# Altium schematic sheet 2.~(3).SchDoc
size 420 x 297 mm
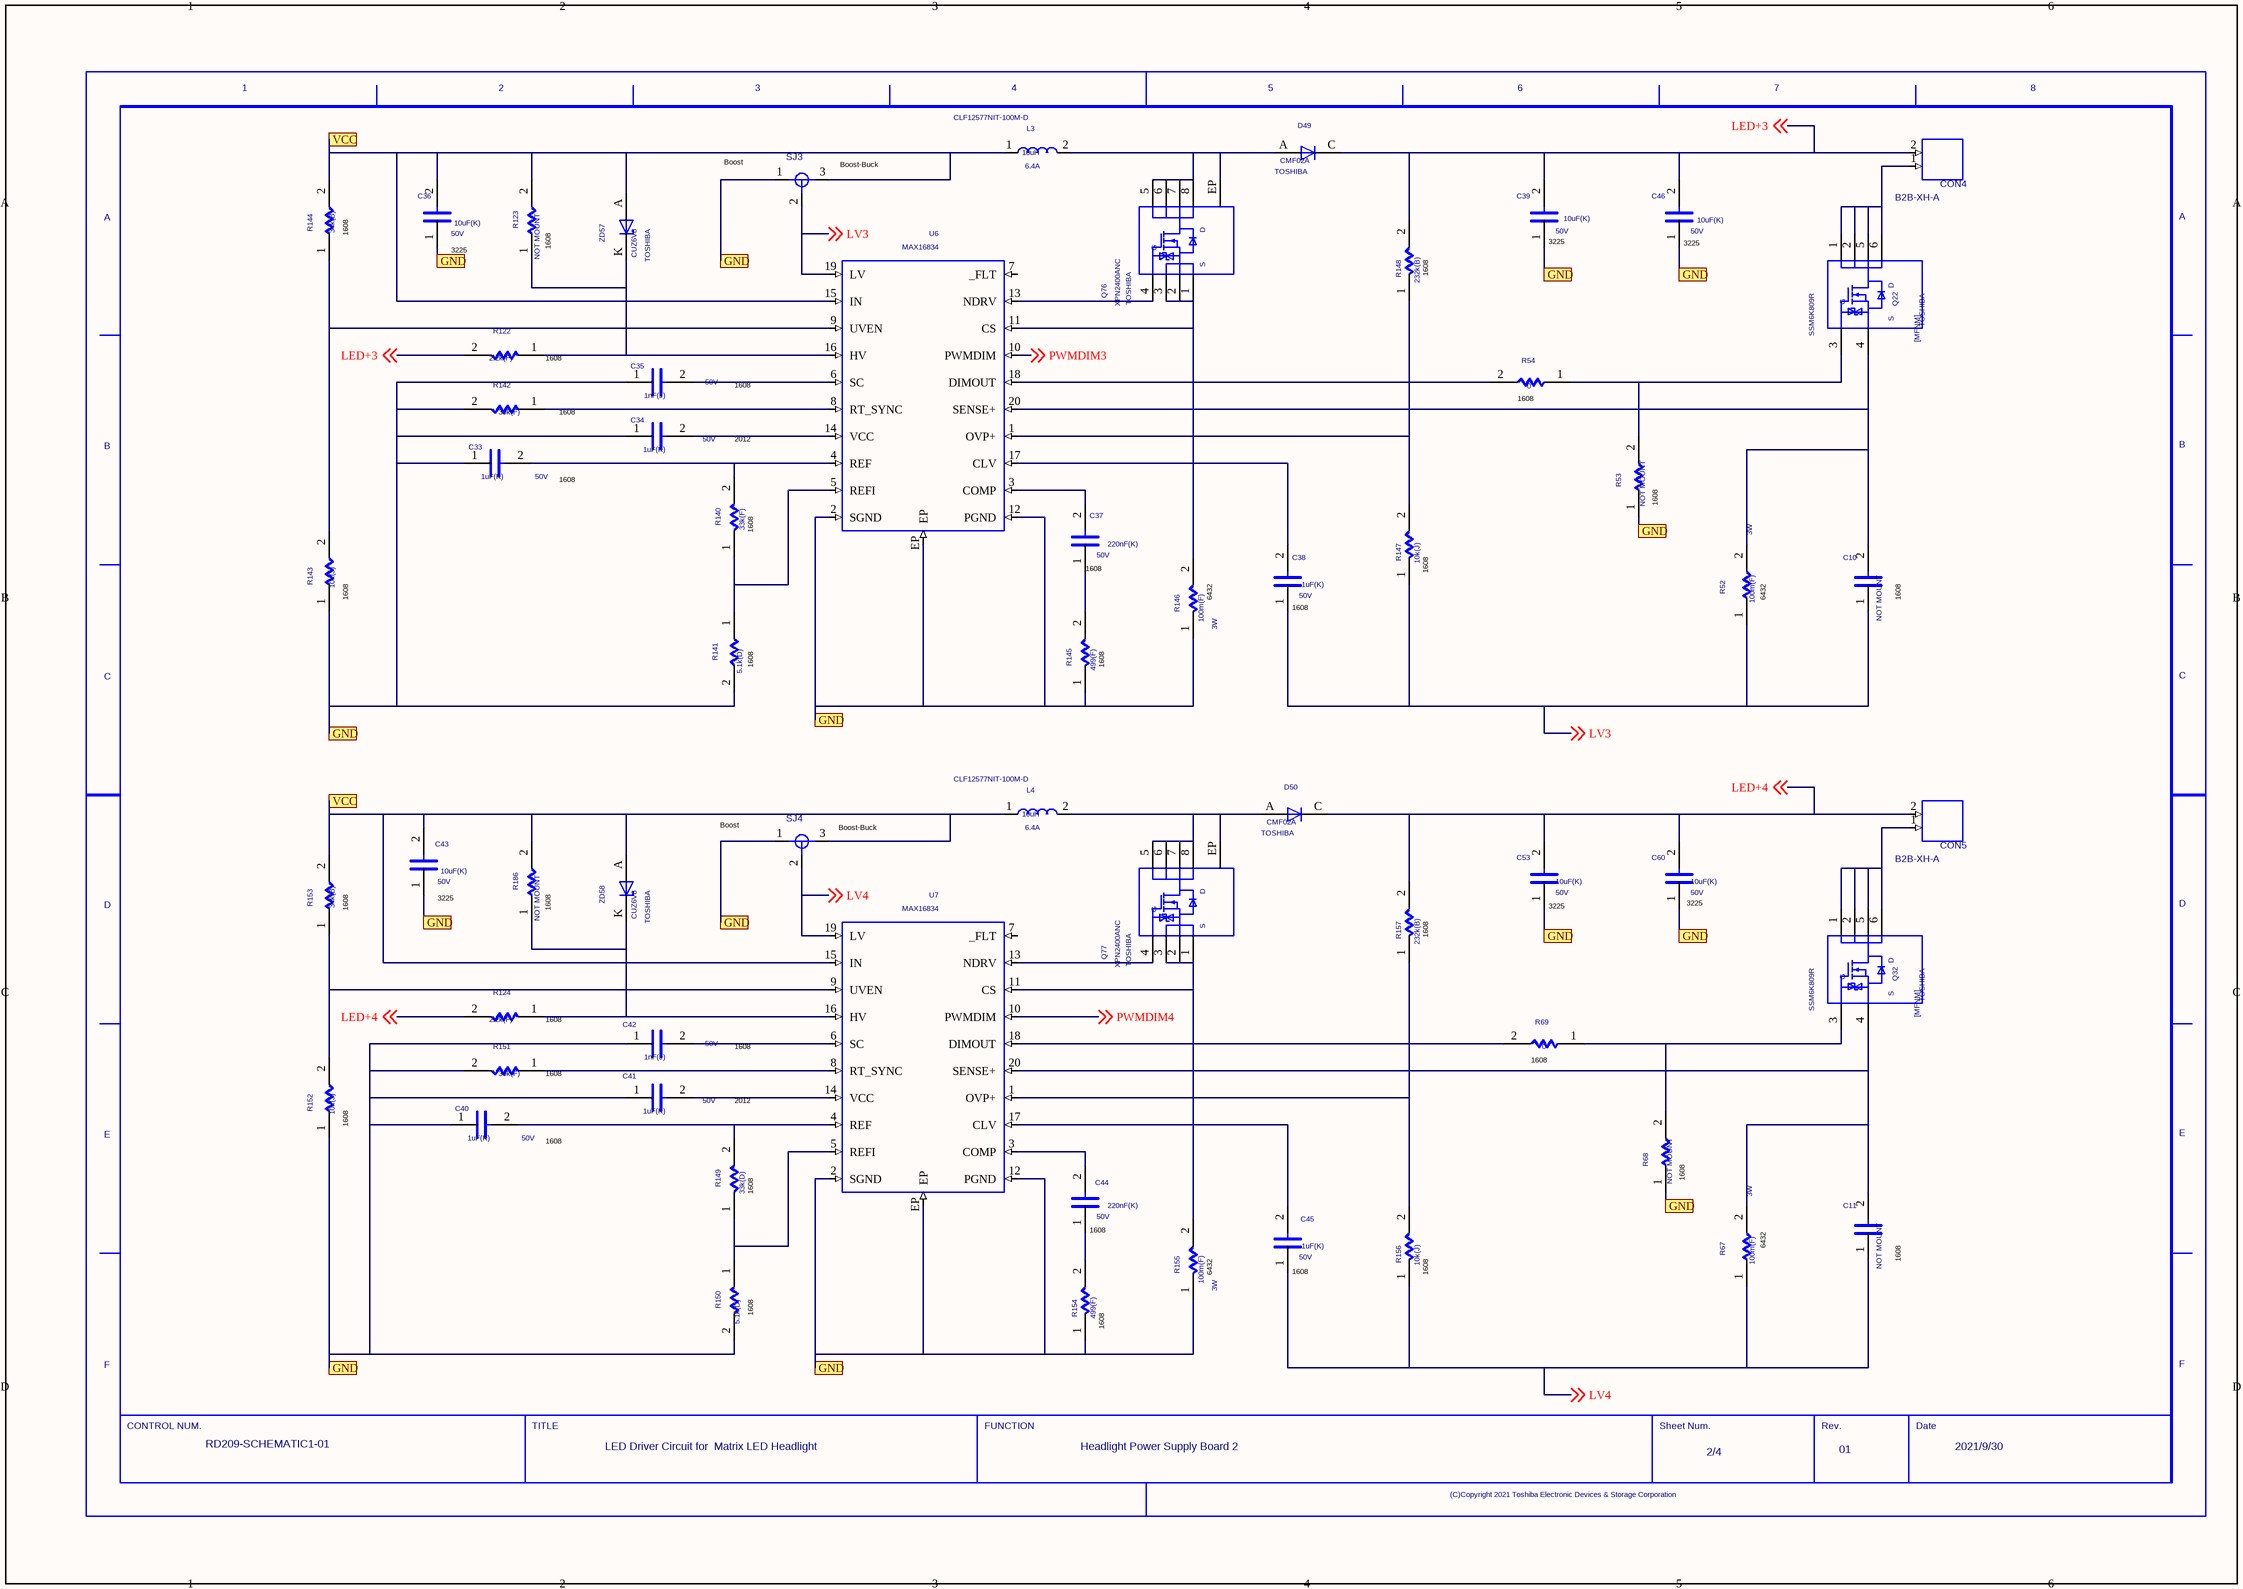
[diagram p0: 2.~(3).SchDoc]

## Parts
C10  NOTMOUNT: NOT MOUNT  (hidden comment: C)
C11  NOTMOUNT: NOT MOUNT  (hidden comment: C)
C33  VAL2: 50V  VAL1: 1uF(K)  (hidden comment: C)
C34  VAL2: 50V  VAL1: 1uF(K)  (hidden comment: C)
C35  VAL2: 50V  VAL1: 1nF(J)  (hidden comment: C)
C36  VAL2: 50V  VAL1: 10uF(K)  (hidden comment: C)
C37  VAL2: 50V  VAL1: 220nF(K)  (hidden comment: C)
C38  VAL2: 50V  VAL1: 1uF(K)  (hidden comment: C)
C39  VAL2: 50V  VAL1: 10uF(K)  (hidden comment: C)
C40  VAL2: 50V  VAL1: 1uF(K)  (hidden comment: C)
C41  VAL2: 50V  VAL1: 1uF(K)  (hidden comment: C)
C42  VAL2: 50V  VAL1: 1nF(J)  (hidden comment: C)
C43  VAL2: 50V  VAL1: 10uF(K)  (hidden comment: C)
C44  VAL2: 50V  VAL1: 220nF(K)  (hidden comment: C)
C45  VAL2: 50V  VAL1: 1uF(K)  (hidden comment: C)
C46  VAL2: 50V  VAL1: 10uF(K)  (hidden comment: C)
C53  VAL2: 50V  VAL1: 10uF(K)  (hidden comment: C)
C60  VAL2: 50V  VAL1: 10uF(K)  (hidden comment: C)
CON4  B2B-XH-A  [B2B-XH-A]
CON5  B2B-XH-A  [B2B-XH-A]
D49  USERCOMPTEXT3: TOSHIBA  VAL3: CMF02A  (hidden comment: D)
D50  USERCOMPTEXT3: TOSHIBA  VAL3: CMF02A  (hidden comment: D)
L3  VAL3: CLF12577NIT-100M-D  VAL2: 6.4A  VAL1: 10uH  (hidden comment: L)
L4  VAL3: CLF12577NIT-100M-D  VAL2: 6.4A  VAL1: 10uH  (hidden comment: L)
Q22  USERCOMPTEXT3: TOSHIBA  VAL3: SSM6K809R  (hidden comment: MFNM)
Q32  USERCOMPTEXT3: TOSHIBA  VAL3: SSM6K809R  (hidden comment: MFNM)
Q76  USERCOMPTEXT3: TOSHIBA  VAL3: XPN2400ANC  (hidden comment: MFNKR1)
Q77  USERCOMPTEXT3: TOSHIBA  VAL3: XPN2400ANC  (hidden comment: MFNKR1)
R52  VAL2: 3W  VAL1: 100m(F)  (hidden comment: R)
R53  NOTMOUNT: NOT MOUNT  (hidden comment: R)
R54  VAL1: 0  (hidden comment: R)
R67  VAL2: 3W  VAL1: 100m(F)  (hidden comment: R)
R68  NOTMOUNT: NOT MOUNT  (hidden comment: R)
R69  VAL1: 0  (hidden comment: R)
R122  VAL1: 2.2k(F)  (hidden comment: R)
R123  NOTMOUNT: NOT MOUNT  (hidden comment: R)
R124  VAL1: 2.2k(F)  (hidden comment: R)
R140  VAL1: 33k(F)  (hidden comment: R)
R141  VAL1: 5.1k(D)  (hidden comment: R)
R142  VAL1: 39k(F)  (hidden comment: R)
R143  VAL1: 10k(J)  (hidden comment: R)
R144  VAL1: 34k(B)  (hidden comment: R)
R145  VAL1: 499(F)  (hidden comment: R)
R146  VAL2: 3W  VAL1: 100m(F)  (hidden comment: R)
R147  VAL1: 10k(J)  (hidden comment: R)
R148  VAL1: 232k(B)  (hidden comment: R)
R149  VAL1: 33k(D)  (hidden comment: R)
R150  VAL1: 5.1k(D)  (hidden comment: R)
R151  VAL1: 39k(F)  (hidden comment: R)
R152  VAL1: 10k(J)  (hidden comment: R)
R153  VAL1: 34k(B)  (hidden comment: R)
R154  VAL1: 499(F)  (hidden comment: R)
R155  VAL2: 3W  VAL1: 100m(F)  (hidden comment: R)
R156  VAL1: 10k(J)  (hidden comment: R)
R157  VAL1: 232k(B)  (hidden comment: R)
R186  NOTMOUNT: NOT MOUNT  (hidden comment: R)
SJ3  SJ2W  (value not drawn)
SJ4  SJ2W  (value not drawn)
U6  MAX16834
U7  MAX16834
U?  DATE: 2021/9/30  REVISION: 01  FUNCTION: Headlight Power Supply Board 2  SHEETNUMBER: 2/4  TITLE: LED Driver Circuit for / Matrix LED Headlight  DRAWINGNUMBER: RD209-SCHEMATIC1-01  (hidden comment: WAKU_DEF100)
ZD57  USERCOMPTEXT3: TOSHIBA  VAL3: CUZ6V8  (hidden comment: ZD)
ZD58  USERCOMPTEXT3: TOSHIBA  VAL3: CUZ6V8  (hidden comment: ZD)

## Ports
GND, VCC

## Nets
GND: C33.1 C34.1 C35.1 C36.1 C39.1 C40.1 C41.1 C42.1 C43.1 C46.1 C53.1 C60.1 R53.1 R68.1 R141.2 R142.2 R143.1 R145.1 R146.1 R150.2 R151.2 R152.1 R154.1 R155.1 SJ3.1 SJ4.1 U6.2(SGND) U6.12(PGND) U6.EP U7.2(SGND) U7.12(PGND) U7.EP ; port GND
LED+3: C39.2 C46.2 CON4.2 D49.C R122.2 R148.2 ; off-sheet LED+3
LED+4: C53.2 C60.2 CON5.2 D50.C R124.2 R157.2 ; off-sheet LED+4
LV3: C10.1 C38.1 R52.1 R147.1 SJ3.2 U6.19(LV) ; off-sheet LV3
LV4: C11.1 C45.1 R67.1 R156.1 SJ4.2 U7.19(LV) ; off-sheet LV4
PWMDIM3: U6.10(PWMDIM) ; off-sheet PWMDIM3
PWMDIM4: U7.10(PWMDIM) ; off-sheet PWMDIM4
SIG668: R142.1 U6.8(RT_SYNC)
SIG669: Q77.1 Q77.2 Q77.3 R155.2 U7.11(CS)
SIG670: D50.A L4.2 Q77.5 Q77.6 Q77.7 Q77.8 Q77.EP
SIG671: CON5.1 Q32.1 Q32.2 Q32.5 Q32.6
SIG673: C44.2 U7.3(COMP)
SIG674: C45.2 U7.17(CLV)
SIG675: R156.2 R157.1 U7.1(OVP+)
SIG676: R69.2 U7.18(DIMOUT)
SIG677: R147.2 R148.1 U6.1(OVP+)
SIG679: R143.2 R144.1 U6.9(UVEN)
SIG680: R151.1 U7.8(RT_SYNC)
SIG681: C42.2 U7.6(SC)
SIG682: Q32.3 R68.2 R69.1
SIG683: R54.2 U6.18(DIMOUT)
SIG686: R124.1 R186.1 U7.16(HV) ZD58.K(C)
SIG690: R149.1 R150.1 U7.5(REFI)
SIG691: R152.2 R153.1 U7.9(UVEN)
SIG693: C40.2 R149.2 U7.4(REF)
SIG694: Q77.4 U7.13(NDRV)
SIG695: C41.2 U7.14(VCC)
SIG696: C10.2 Q22.4 R52.2 U6.20(SENSE+)
SIG697: D49.A L3.2 Q76.5 Q76.6 Q76.7 Q76.8 Q76.EP
SIG698: R122.1 R123.1 U6.16(HV) ZD57.K(C)
SIG699: Q76.1 Q76.2 Q76.3 R146.2 U6.11(CS)
SIG700: C37.1 R145.2
SIG702: C44.1 R154.2
SIG704: Q22.3 R53.2 R54.1
SIG705: CON4.1 Q22.1 Q22.2 Q22.5 Q22.6
SIG707: R140.1 R141.1 U6.5(REFI)
SIG709: C11.2 Q32.4 R67.2 U7.20(SENSE+)
SIG710: C37.2 U6.3(COMP)
SIG711: C35.2 U6.6(SC)
SIG712: C33.2 R140.2 U6.4(REF)
SIG713: C38.2 U6.17(CLV)
SIG715: C34.2 U6.14(VCC)
SIG717: Q76.4 U6.13(NDRV)
VCC: C36.2 C43.2 L3.1 L4.1 R123.2 R144.2 R153.2 R186.2 SJ3.3 SJ4.3 U6.15(IN) U7.15(IN) ZD57.A ZD58.A ; port VCC

Not connected (* = marked no-connect by the designer): U6 7(_FLT); U7 7(_FLT)

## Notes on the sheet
- (near SJ3) Boost
- (near SJ3) Boost-Buck
- (near R144) 1608
- (near C36) 3225
- (near R123) 1608
- (near C39) 3225
- (near C46) 3225
- (near R148) 1608
- (near R122) 1608
- 1608
- (near R142) 1608
- 2012
- (near R54) 1608
- (near R140) 1608
- (near R53) 1608
- (near R143) 1608
- (near C37) 1608
- (near R146) 6432
- (near R147) 1608
- (near R52) 6432
- (near C10) 1608
- (near R141) 1608
- (near R145) 1608
- (near C38) 1608
- (near SJ4) Boost
- (near SJ4) Boost-Buck
- (near R153) 1608
- (near C43) 3225
- (near R186) 1608
- (near R157) 1608
- (near C53) 3225
- (near C60) 3225
- (near R124) 1608
- (near R69) 1608
- (near R152) 1608
- (near R151) 1608
- (near R149) 1608
- (near R68) 1608
- (near C44) 1608
- (near R155) 6432
- (near C45) 1608
- (near R156) 1608
- (near R67) 6432
- (near C11) 1608
- (near R150) 1608
- (near R154) 1608

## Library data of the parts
C10 = C: TIME: 17:22:43; UPDATEUSER: t5459927; SAVECOUNT: 1; OriginalSymbolOrigin: (2540,7620); INSTANCENAME: cmp621; CDBNAME: C0603K
C11 = C: TIME: 17:22:43; UPDATEUSER: t5459927; SAVECOUNT: 1; OriginalSymbolOrigin: (2540,7620); INSTANCENAME: cmp618; CDBNAME: C0603K
C33 = C: TIME: 17:22:43; UPDATEUSER: t5459927; SAVECOUNT: 1; OriginalSymbolOrigin: (2540,7620); INSTANCENAME: cmp640; CDBNAME: C0603K_3
C34 = C: TIME: 17:22:43; UPDATEUSER: t5459927; SAVECOUNT: 1; OriginalSymbolOrigin: (2540,7620); INSTANCENAME: cmp563; CDBNAME: C0805K_1
C35 = C: TIME: 17:22:43; UPDATEUSER: t5459927; SAVECOUNT: 1; OriginalSymbolOrigin: (2540,7620); INSTANCENAME: cmp588; CDBNAME: C0603K_1
C36 = C: TIME: 17:22:43; UPDATEUSER: t5459927; SAVECOUNT: 1; OriginalSymbolOrigin: (2540,7620); INSTANCENAME: cmp623; CDBNAME: C1210K
C37 = C: TIME: 17:22:43; UPDATEUSER: t5459927; SAVECOUNT: 1; OriginalSymbolOrigin: (2540,7620); INSTANCENAME: cmp596; CDBNAME: C0603K_4
C38 = C: TIME: 17:22:43; UPDATEUSER: t5459927; SAVECOUNT: 1; OriginalSymbolOrigin: (2540,7620); INSTANCENAME: cmp624; CDBNAME: C0603K_3
C39 = C: TIME: 17:22:43; UPDATEUSER: t5459927; SAVECOUNT: 1; OriginalSymbolOrigin: (2540,7620); INSTANCENAME: cmp589; CDBNAME: C1210K
C40 = C: TIME: 17:22:43; UPDATEUSER: t5459927; SAVECOUNT: 1; OriginalSymbolOrigin: (2540,7620); INSTANCENAME: cmp634; CDBNAME: C0603K_3
C41 = C: TIME: 17:22:43; UPDATEUSER: t5459927; SAVECOUNT: 1; OriginalSymbolOrigin: (2540,7620); INSTANCENAME: cmp629; CDBNAME: C0805K_1
C42 = C: TIME: 17:22:43; UPDATEUSER: t5459927; SAVECOUNT: 1; OriginalSymbolOrigin: (2540,7620); INSTANCENAME: cmp601; CDBNAME: C0603K_1
C43 = C: TIME: 17:22:43; UPDATEUSER: t5459927; SAVECOUNT: 1; OriginalSymbolOrigin: (2540,7620); INSTANCENAME: cmp574; CDBNAME: C1210K
C44 = C: TIME: 17:22:43; UPDATEUSER: t5459927; SAVECOUNT: 1; OriginalSymbolOrigin: (2540,7620); INSTANCENAME: cmp606; CDBNAME: C0603K_4
C45 = C: TIME: 17:22:43; UPDATEUSER: t5459927; SAVECOUNT: 1; OriginalSymbolOrigin: (2540,7620); INSTANCENAME: cmp592; CDBNAME: C0603K_3
C46 = C: TIME: 17:22:43; UPDATEUSER: t5459927; SAVECOUNT: 1; OriginalSymbolOrigin: (2540,7620); INSTANCENAME: cmp643; CDBNAME: C1210K
C53 = C: TIME: 17:22:43; UPDATEUSER: t5459927; SAVECOUNT: 1; OriginalSymbolOrigin: (2540,7620); INSTANCENAME: cmp642; CDBNAME: C1210K
C60 = C: TIME: 17:22:43; UPDATEUSER: t5459927; SAVECOUNT: 1; OriginalSymbolOrigin: (2540,7620); INSTANCENAME: cmp627; CDBNAME: C1210K
CON4 CON5 = B2B_XH_A: SAVECOUNT: 1; COMP: B2_BX_HA; UPDATEUSER: t5459927; UPDATETIME: 17:22:42; OriginalSymbolOrigin: (0,0); COMPONENTNAME: CON; INSTANCENAME: INS9160
D49 D50 = D: SAVEAREA0: -225,-91,12804,7836; SAVECOUNT: 3; TIME: 14:49:55; UPDATEUSER: 19870035; UPDATETIME: 14:20:16; OriginalSymbolOrigin: (5080,5080); CDBNAME: M-FLAT
L3 = L: COMP: CLF12577NI_D; TIME: 17:22:43; UPDATEUSER: t5459927; SAVECOUNT: 1; OriginalSymbolOrigin: (2540,5080); INSTANCENAME: cmp573; CDBNAME: CLF12577NI-D
L4 = L: COMP: CLF12577NI_D; TIME: 17:22:43; UPDATEUSER: t5459927; SAVECOUNT: 1; OriginalSymbolOrigin: (2540,5080); INSTANCENAME: cmp646; CDBNAME: CLF12577NI-D
Q22 = MFNM: TIME: 17:22:43; SAVECOUNT: 1; SAVEAREA0: -6986,-322,29385,23602; UPDATEUSER: t5459927; OriginalSymbolOrigin: (5080,20320); COMPONENTNAME: Q; INSTANCENAME: cmp648; CDBNAME: TSOP6F
Q32 = MFNM: TIME: 17:22:43; SAVECOUNT: 1; SAVEAREA0: -6986,-322,29385,23602; UPDATEUSER: t5459927; OriginalSymbolOrigin: (5080,20320); COMPONENTNAME: Q; INSTANCENAME: cmp571; CDBNAME: TSOP6F
Q76 Q77 = MFNKR1: TIME: 17:22:43; SAVECOUNT: 2; SAVEAREA0: -5755,-491,27794,24105; COMP: TSON_ADVANCE_WF_1; UPDATETIME: 09:26:31; UPDATEUSER: t5459927; OriginalSymbolOrigin: (5080,20320); COMPONENTNAME: Q
R52 = R: TIME: 17:22:43; UPDATEUSER: t5459927; SAVECOUNT: 1; OriginalSymbolOrigin: (5080,5080); INSTANCENAME: cmp587; CDBNAME: R2512
R53 = R: TIME: 17:22:43; UPDATEUSER: t5459927; SAVECOUNT: 1; OriginalSymbolOrigin: (5080,5080); INSTANCENAME: cmp639; CDBNAME: R0603
R54 = R: TIME: 17:22:43; UPDATEUSER: t5459927; SAVECOUNT: 1; OriginalSymbolOrigin: (5080,5080); INSTANCENAME: cmp605; CDBNAME: R0603_7
R67 = R: TIME: 17:22:43; UPDATEUSER: t5459927; SAVECOUNT: 1; OriginalSymbolOrigin: (5080,5080); INSTANCENAME: cmp568; CDBNAME: R2512
R68 = R: TIME: 17:22:43; UPDATEUSER: t5459927; SAVECOUNT: 1; OriginalSymbolOrigin: (5080,5080); INSTANCENAME: cmp636; CDBNAME: R0603
R69 = R: TIME: 17:22:43; UPDATEUSER: t5459927; SAVECOUNT: 1; OriginalSymbolOrigin: (5080,5080); INSTANCENAME: cmp595; CDBNAME: R0603_7
R122 = R: TIME: 17:22:43; UPDATEUSER: t5459927; SAVECOUNT: 1; OriginalSymbolOrigin: (5080,5080); VAL2: 100mW; INSTANCENAME: cmp617; CDBNAME: R0603_2
R123 = R: TIME: 17:22:43; UPDATEUSER: t5459927; SAVECOUNT: 1; OriginalSymbolOrigin: (5080,5080); INSTANCENAME: cmp598; CDBNAME: R0603
R124 = R: TIME: 17:22:43; UPDATEUSER: t5459927; SAVECOUNT: 1; OriginalSymbolOrigin: (5080,5080); VAL2: 100mW; INSTANCENAME: cmp619; CDBNAME: R0603_2
R140 = R#1: TIME: 17:22:43; UPDATEUSER: t5459927; SAVECOUNT: 1; OriginalSymbolOrigin: (5080,5080); CaptureCellPackProp: R##1; VAL2: 100mW; INSTANCENAME: cmp630; CDBNAME: R0603_11
R141 = R: TIME: 17:22:43; UPDATEUSER: t5459927; SAVECOUNT: 1; OriginalSymbolOrigin: (5080,5080); VAL2: 100mW; INSTANCENAME: cmp599; CDBNAME: R0603_10
R142 = R: TIME: 17:22:43; UPDATEUSER: t5459927; SAVECOUNT: 1; OriginalSymbolOrigin: (5080,5080); VAL2: 100mW; INSTANCENAME: cmp580; CDBNAME: R0603_8
R143 = R: TIME: 17:22:43; UPDATEUSER: t5459927; SAVECOUNT: 1; OriginalSymbolOrigin: (5080,5080); VAL2: 100mW; INSTANCENAME: cmp590; CDBNAME: R0603_6
R144 = R: TIME: 17:22:43; UPDATEUSER: t5459927; SAVECOUNT: 1; OriginalSymbolOrigin: (5080,5080); VAL2: 100mW; INSTANCENAME: cmp616; CDBNAME: R0603_1
R145 = R: TIME: 17:22:43; UPDATEUSER: t5459927; SAVECOUNT: 1; OriginalSymbolOrigin: (5080,5080); VAL2: 125mW; INSTANCENAME: cmp614; CDBNAME: R0603_12
R146 = R: TIME: 17:22:43; UPDATEUSER: t5459927; SAVECOUNT: 1; OriginalSymbolOrigin: (5080,5080); INSTANCENAME: cmp631; CDBNAME: R2512
R147 = R: TIME: 17:22:43; UPDATEUSER: t5459927; SAVECOUNT: 1; OriginalSymbolOrigin: (5080,5080); VAL2: 100mW; INSTANCENAME: cmp608; CDBNAME: R0603_6
R148 = R: TIME: 17:22:43; UPDATEUSER: t5459927; SAVECOUNT: 1; OriginalSymbolOrigin: (5080,5080); VAL2: 63mW; INSTANCENAME: cmp625; CDBNAME: R0603_9
R149 = R#1: TIME: 17:22:43; UPDATEUSER: t5459927; SAVECOUNT: 1; OriginalSymbolOrigin: (5080,5080); CaptureCellPackProp: R##1; VAL2: 100mW; INSTANCENAME: cmp612; CDBNAME: R0603_11
R150 = R: TIME: 17:22:43; UPDATEUSER: t5459927; SAVECOUNT: 1; OriginalSymbolOrigin: (5080,5080); VAL2: 100mW; INSTANCENAME: cmp594; CDBNAME: R0603_10
R151 = R: TIME: 17:22:43; UPDATEUSER: t5459927; SAVECOUNT: 1; OriginalSymbolOrigin: (5080,5080); VAL2: 100mW; INSTANCENAME: cmp583; CDBNAME: R0603_8
R152 = R: TIME: 17:22:43; UPDATEUSER: t5459927; SAVECOUNT: 1; OriginalSymbolOrigin: (5080,5080); VAL2: 100mW; INSTANCENAME: cmp577; CDBNAME: R0603_6
R153 = R: TIME: 17:22:43; UPDATEUSER: t5459927; SAVECOUNT: 1; OriginalSymbolOrigin: (5080,5080); VAL2: 100mW; INSTANCENAME: cmp610; CDBNAME: R0603_1
R154 = R: TIME: 17:22:43; UPDATEUSER: t5459927; SAVECOUNT: 1; OriginalSymbolOrigin: (5080,5080); VAL2: 125mW; INSTANCENAME: cmp604; CDBNAME: R0603_12
R155 = R: TIME: 17:22:43; UPDATEUSER: t5459927; SAVECOUNT: 1; OriginalSymbolOrigin: (5080,5080); INSTANCENAME: cmp597; CDBNAME: R2512
R156 = R: TIME: 17:22:43; UPDATEUSER: t5459927; SAVECOUNT: 1; OriginalSymbolOrigin: (5080,5080); VAL2: 100mW; INSTANCENAME: cmp586; CDBNAME: R0603_6
R157 = R: TIME: 17:22:43; UPDATEUSER: t5459927; SAVECOUNT: 1; OriginalSymbolOrigin: (5080,5080); VAL2: 63mW; INSTANCENAME: cmp611; CDBNAME: R0603_9
R186 = R: TIME: 17:22:43; UPDATEUSER: t5459927; SAVECOUNT: 1; OriginalSymbolOrigin: (5080,5080); INSTANCENAME: cmp644; CDBNAME: R0603
SJ3 = SJ2W: SAVECOUNT: 1; COMP: SJ_2; SAVEAREA0: -15743,-4510,23437,11881; UPDATEUSER: t5459927; UPDATETIME: 17:22:42; OriginalSymbolOrigin: (2540,7620); COMPONENTNAME: SJ; INSTANCENAME: cmp613
SJ4 = SJ2W: SAVECOUNT: 1; COMP: SJ_2; SAVEAREA0: -15743,-4510,23437,11881; UPDATEUSER: t5459927; UPDATETIME: 17:22:42; OriginalSymbolOrigin: (2540,7620); COMPONENTNAME: SJ; INSTANCENAME: cmp566
U6 U7 = MAX16834: SAVECOUNT: 1; COMP: 20-TQFN; SAVEAREA0: -47937,-54417,76568,2975; UPDATEUSER: t5459927; UPDATETIME: 17:22:42; OriginalSymbolOrigin: (0,0); COMPONENTNAME: IC; INSTANCENAME: cmp580
U? = WAKU_DEF100: PLOTTIME: HH:MM; SAVEAREA0: 147884,-66467,487065,89883; TIME: 14:30:25; UPDATEUSER: t5459927; UPDATETIME: 12:50:54; SAVECOUNT: 7; OriginalSymbolOrigin: (10160,284480)
ZD57 = ZD: TIME: 17:22:43; SAVECOUNT: 1; SAVEAREA0: -4630,-153,17114,13055; UPDATEUSER: t5459927; OriginalSymbolOrigin: (5080,5080); INSTANCENAME: cmp582; CDBNAME: USC
ZD58 = ZD: TIME: 17:22:43; SAVECOUNT: 1; SAVEAREA0: -4630,-153,17114,13055; UPDATEUSER: t5459927; OriginalSymbolOrigin: (5080,5080); INSTANCENAME: cmp593; CDBNAME: USC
